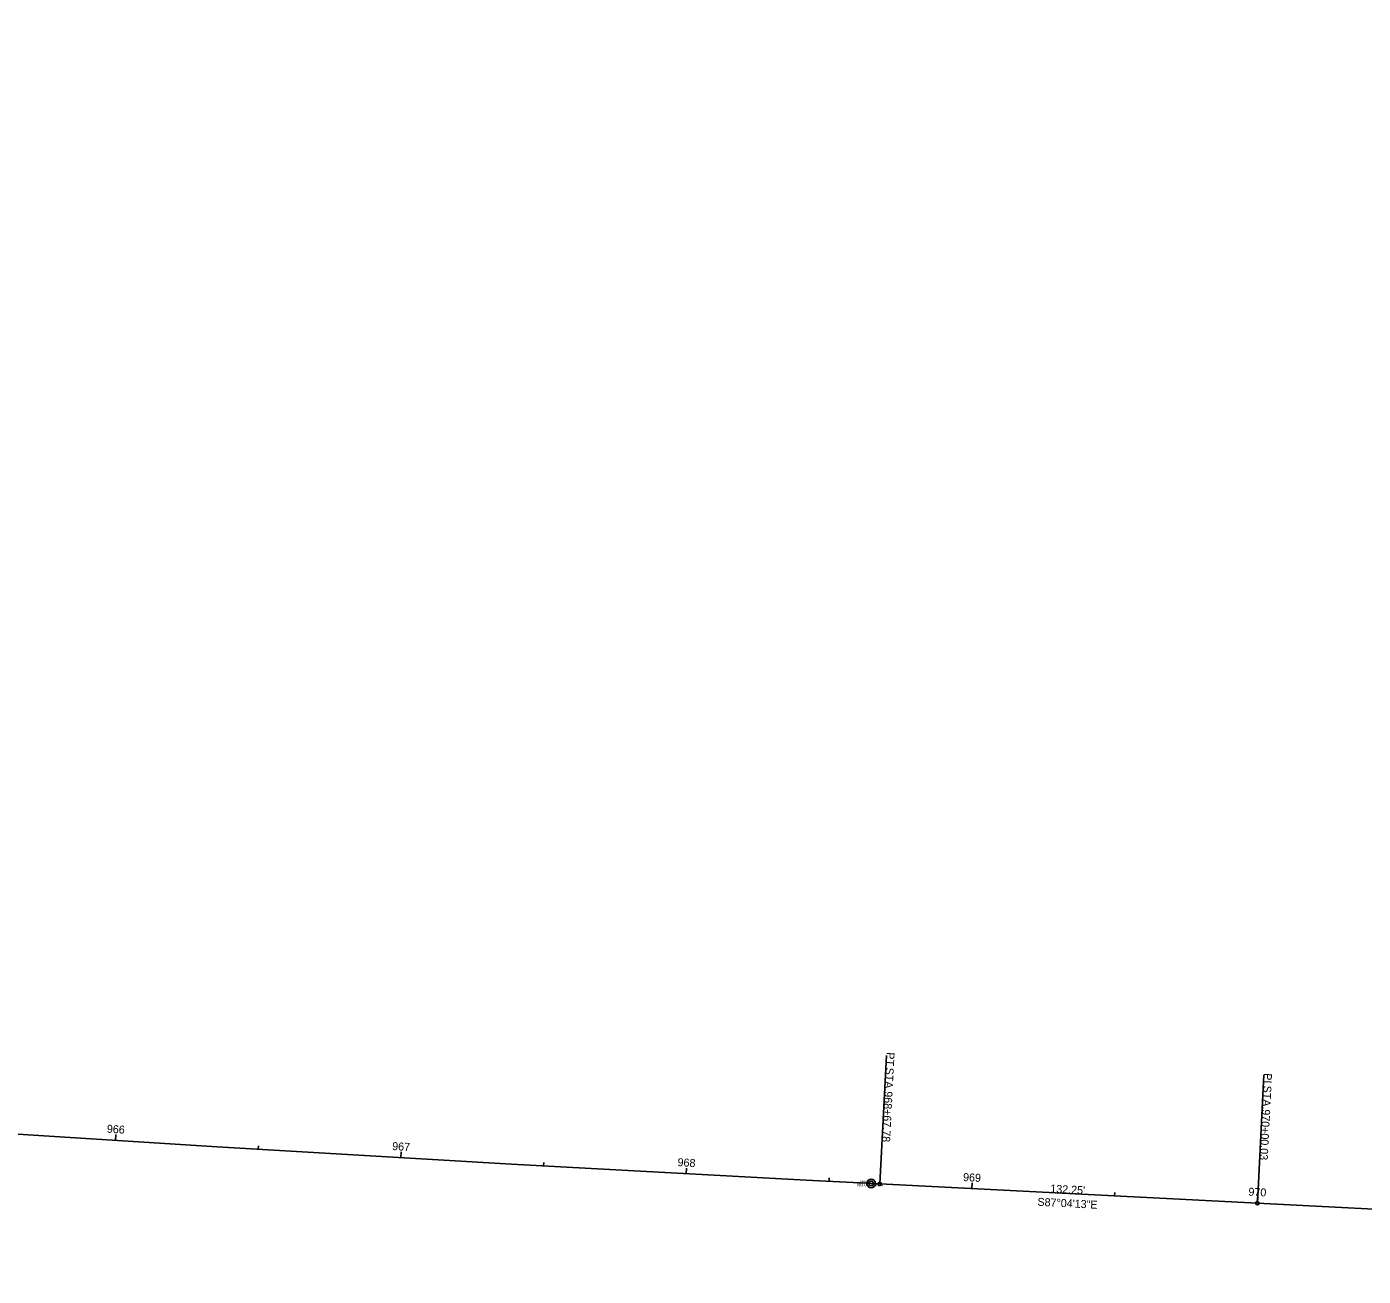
# Model space of a CAD drawing. Extents: x 2061744 to 2069155, y 709240 to 710416.
# Drawn here: x 2068219.8 to 2068687.3, y 709241 to 709678.2 of the extents above; entities that cross this region are included whole.
import ezdxf

# ---------------------------------------------------------------- set-up
doc = ezdxf.new("R2010")
doc.units = 0
for name, color, linetype in [('RS_Raster1', 7, 'Continuous'), ('RW_X_CL', 7, 'Continuous'), ('RW_X_CL_100_Bearings', 7, 'Continuous'), ('RW_X_CL_100_Cardinal_Points', 7, 'Continuous'), ('RW_X_CL_100_Distances', 7, 'Continuous'), ('RW_X_CL_100_Stations', 7, 'Continuous'), ('SV_X_Mon_Cells_Found', 7, 'Continuous'), ('SV_X_Text_Comment', 7, 'Continuous'), ('SV_X_Text_Elevation', 7, 'Continuous'), ('SV_X_Text_Name', 7, 'Continuous')]:
    doc.layers.add(name, color=color, linetype=linetype)

msp = doc.modelspace()

# ---------------------------------------------------------------- linework, layer by layer
at = {"layer": 'RS_Raster1'}
for p, q in [((2068518.16, 709273.3), (2068650.24, 709266.54)), ((2068650.24, 709266.54), (2069149.58, 709240.99))]:
    msp.add_line(p, q, dxfattribs=at)
msp.add_arc((2069689.49, 732161.85), 22918.5, 258.820408, 267.070408, dxfattribs=at)
at = {"layer": 'RW_X_CL'}
for p, q in [((2068518.16, 709273.3), (2068650.24, 709266.54)), ((2068650.24, 709266.54), (2069149.58, 709240.99))]:
    msp.add_line(p, q, dxfattribs=at)
msp.add_arc((2069689.49, 732161.85), 22918.5, 258.820408, 267.070408, dxfattribs=at)
at = {"layer": 'RW_X_CL_100_Cardinal_Points'}
for p, q in [((2068518.16, 709273.3), (2068520.46, 709318.24)), ((2068650.24, 709266.54), (2068652.54, 709311.48))]:
    msp.add_line(p, q, dxfattribs=at)
for centre in [(2068518.16, 709273.3), (2068650.24, 709266.54)]:
    msp.add_circle(centre, 0.6, dxfattribs=at)
at = {"layer": 'RW_X_CL_100_Stations'}
for p, q in [((2068250.82, 709288.55), (2068250.94, 709290.55)), ((2068300.72, 709285.47), (2068300.8, 709286.66)), ((2068350.63, 709282.49), (2068350.75, 709284.49)), ((2068400.55, 709279.62), (2068400.62, 709280.82)), ((2068450.48, 709276.87), (2068450.58, 709278.86)), ((2068500.41, 709274.22), (2068500.47, 709275.42)), ((2068550.34, 709271.65), (2068550.44, 709273.65)), ((2068600.27, 709269.1), (2068600.34, 709270.3)), ((2068650.21, 709266.54), (2068650.31, 709268.54))]:
    msp.add_line(p, q, dxfattribs=at)
at = {"layer": 'SV_X_Mon_Cells_Found'}
for radius in [1.5, 0.8]:
    msp.add_circle((2068515.14, 709273.49), radius, dxfattribs=at)

# ---------------------------------------------------------------- texts
at = {"layer": 'RW_X_CL_100_Bearings'}
msp.add_text('S87°04\'13"E', height=2.8, rotation=357.0704, dxfattribs=at).set_placement((2068573.26, 709265.68))
at = {"layer": 'RW_X_CL_100_Cardinal_Points'}
for s, p in [('PT', (2068520.56, 709319.43)), (' STA. ', (2068520.33, 709315.09)), ('PI', (2068652.6, 709312.11)), ('968+67.78', (2068519.86, 709305.78)), (' STA. ', (2068652.43, 709308.79)), ('970+00.03', (2068651.96, 709299.48))]:
    msp.add_text(s, height=2.8, rotation=267.0704, dxfattribs=at).set_placement(p)
at = {"layer": 'RW_X_CL_100_Distances'}
msp.add_text("132.25'", height=2.8, rotation=357.0704, dxfattribs=at).set_placement((2068577.77, 709270.29))
at = {"layer": 'RW_X_CL_100_Stations'}
for s, rotation, p in [('966', 356.401, (2068247.73, 709291.25)), ('967', 356.651, (2068347.54, 709285.17)), ('968', 356.901, (2068447.37, 709279.54)), ('969', 357.0704, (2068547.25, 709274.32)), ('970', 357.0704, (2068647.07, 709269.21))]:
    msp.add_text(s, height=2.8, rotation=rotation, dxfattribs=at).set_placement(p)
at = {"layer": 'SV_X_Text_Comment'}
msp.add_text('CMON', height=1, dxfattribs=at).set_placement((2068515.14, 709272.49))
at = {"layer": 'SV_X_Text_Elevation'}
msp.add_text('993.065', height=1, dxfattribs=at).set_placement((2068510.07, 709272.49))
at = {"layer": 'SV_X_Text_Name'}
msp.add_text('MN08', height=1, dxfattribs=at).set_placement((2068511.28, 709273.49))

doc.saveas('drawing.dxf')
